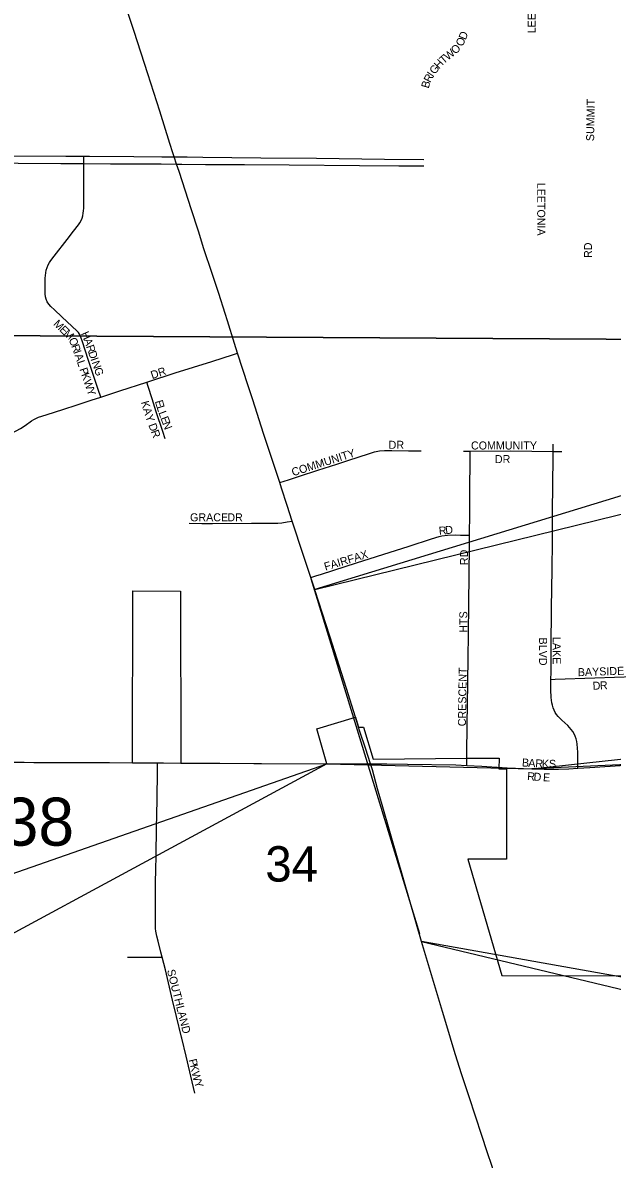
# Model space of a CAD drawing. Extents: x -9.1 to 34, y -3.1 to 22.
# Drawn here: x 5.401 to 6.099, y 17.795 to 19.14 of the extents above; entities that cross this region are included whole.
import ezdxf

# ---------------------------------------------------------------- set-up
doc = ezdxf.new("R2010")
doc.units = 0
for name, color, linetype in [('GM_X_City_Street', 7, 'Continuous'), ('GM_X_City_Street_Text', 7, 'Continuous'), ('GM_X_Corporation', 7, 'Continuous'), ('GM_X_County_Road', 7, 'Continuous'), ('GM_X_County_Road_Text', 7, 'Continuous'), ('GM_X_Section', 7, 'Continuous'), ('GM_X_Section_Text', 7, 'Continuous'), ('GM_X_State_Route', 7, 'Continuous'), ('GM_X_Township_Subdivision', 7, 'Continuous'), ('GM_X_Township_Subdivision_Text', 7, 'Continuous'), ('SH_Data', 7, 'Continuous'), ('SH_Text', 7, 'Continuous')]:
    doc.layers.add(name, color=color, linetype=linetype)

msp = doc.modelspace()

# ---------------------------------------------------------------- linework, layer by layer
at = {"layer": 'GM_X_City_Street'}
for points in [[(5.3542, 18.9769), (5.356, 18.9783), (5.3586, 18.9798), (5.3615, 18.9809), (5.3636, 18.9814), (5.3652, 18.9818), (5.3667, 18.9822), (5.3681, 18.9824), (5.3713, 18.9826), (5.3788, 18.9827), (5.4521, 18.9824), (5.4736, 18.9823)], [(5.3542, 18.9769), (5.3606, 18.9753), (5.3623, 18.9749), (5.3637, 18.9748), (5.3658, 18.9747), (5.3698, 18.9745), (5.3751, 18.9744), (5.3959, 18.9741), (5.4463, 18.9738), (5.471, 18.9736), (5.4736, 18.9736)], [(5.4736, 18.9736), (5.4736, 18.977), (5.4736, 18.9823)], [(5.4736, 18.9823), (5.48, 18.9823), (5.5328, 18.9819), (5.5658, 18.9816), (5.5805, 18.9814)], [(5.5805, 18.9814), (5.5956, 18.9814), (5.6143, 18.9813), (5.6487, 18.9809), (5.6831, 18.9805), (5.7489, 18.9799), (5.8294, 18.9787), (5.8757, 18.9785)], [(5.4934, 18.6971), (5.4905, 18.706), (5.4849, 18.7226), (5.4791, 18.7405), (5.4716, 18.7639), (5.4704, 18.767), (5.4694, 18.7696), (5.4683, 18.7718), (5.4671, 18.7735), (5.4656, 18.7751), (5.4476, 18.792), (5.4388, 18.8003), (5.4344, 18.8045), (5.4321, 18.8073), (5.4302, 18.8101), (5.429, 18.813), (5.4282, 18.816), (5.4278, 18.8192), (5.4278, 18.8318), (5.4278, 18.838), (5.428, 18.8412), (5.4283, 18.8444), (5.429, 18.8475), (5.4299, 18.8506), (5.4311, 18.8536), (5.4327, 18.8564), (5.4344, 18.859), (5.4382, 18.864), (5.4538, 18.8836), (5.4614, 18.8935), (5.4671, 18.9009), (5.4688, 18.9034), (5.4702, 18.906), (5.4713, 18.9088), (5.4722, 18.9117), (5.4728, 18.9147), (5.4732, 18.9177), (5.4734, 18.9208), (5.4734, 18.9301), (5.4736, 18.9676), (5.4736, 18.9736)], [(5.4736, 18.9736), (5.505, 18.9734), (5.5351, 18.9733), (5.559, 18.9732), (5.5651, 18.9732), (5.5833, 18.9729)], [(5.5833, 18.9729), (5.5896, 18.9728), (5.6174, 18.9726), (5.6638, 18.9723), (5.7164, 18.972), (5.7999, 18.9714), (5.8463, 18.971), (5.8757, 18.9707)], [(5.548, 18.7149), (5.5494, 18.7153), (5.5816, 18.7258), (5.625, 18.7395), (5.6507, 18.7476), (5.6555, 18.7492)], [(5.4934, 18.6971), (5.5161, 18.7045), (5.548, 18.7149)], [(5.5699, 18.6478), (5.567, 18.6565), (5.5592, 18.6798), (5.5542, 18.695), (5.5496, 18.7098), (5.548, 18.7149)], [(5.3655, 18.652), (5.3754, 18.6521), (5.3785, 18.6523), (5.3816, 18.6529), (5.3846, 18.6537), (5.3875, 18.6546), (5.3904, 18.6558), (5.3932, 18.6571), (5.3987, 18.6601), (5.404, 18.6636), (5.4116, 18.669), (5.4143, 18.6706), (5.4199, 18.6733), (5.4288, 18.6762), (5.4496, 18.6828), (5.4644, 18.6877), (5.4821, 18.6935), (5.4934, 18.6971)], [(6.0291, 18.633), (6.0291, 18.6416)], [(5.7053, 18.5961), (5.7156, 18.5994), (5.7286, 18.6035), (5.7506, 18.6109), (5.7731, 18.618), (5.787, 18.6224), (5.7982, 18.6262), (5.8117, 18.6305), (5.8175, 18.6323), (5.8234, 18.6336), (5.8295, 18.6339), (5.8382, 18.6339), (5.8577, 18.6338), (5.8726, 18.6336)], [(5.923, 18.6333), (5.9307, 18.6333)], [(5.93, 18.5338), (5.9302, 18.5599), (5.9305, 18.5931), (5.9307, 18.6169), (5.9307, 18.6296), (5.9307, 18.6333)], [(5.9307, 18.6333), (5.9787, 18.6335), (6.0038, 18.6333), (6.0289, 18.633), (6.0291, 18.633)], [(6.0264, 18.3631), (6.0265, 18.3717), (6.0265, 18.4002), (6.027, 18.4478), (6.0278, 18.493), (6.028, 18.5262), (6.0282, 18.5611), (6.0291, 18.6261), (6.0291, 18.633)], [(6.0291, 18.633), (6.0393, 18.633)], [(5.5981, 18.5479), (5.6132, 18.5476), (5.6256, 18.5478), (5.672, 18.5481), (5.6905, 18.5481), (5.703, 18.5482), (5.7079, 18.5485), (5.7142, 18.5495), (5.7202, 18.5505)], [(5.742, 18.4839), (5.7492, 18.4861), (5.7537, 18.4874), (5.7694, 18.4925), (5.7961, 18.501), (5.8198, 18.5085), (5.8584, 18.5209), (5.885, 18.5296), (5.894, 18.5322), (5.8971, 18.5329), (5.9038, 18.5338), (5.9128, 18.5341), (5.9191, 18.534), (5.93, 18.5338)], [(5.9267, 18.2612), (5.9267, 18.2645), (5.9269, 18.2751), (5.9272, 18.3093), (5.9281, 18.3588), (5.9284, 18.39), (5.9287, 18.4152), (5.9292, 18.4536), (5.9295, 18.4856), (5.9299, 18.5233), (5.93, 18.5338)], [(6.0582, 18.258), (6.0582, 18.2648), (6.0583, 18.2679), (6.058, 18.2772), (6.0574, 18.2865), (6.057, 18.2896), (6.0562, 18.2927), (6.0552, 18.2958), (6.0539, 18.2987), (6.0522, 18.3014), (6.0503, 18.304), (6.0462, 18.3087), (6.0394, 18.315), (6.035, 18.3193), (6.0331, 18.3216), (6.0315, 18.3241), (6.0301, 18.3268), (6.029, 18.3296), (6.0281, 18.3325), (6.0275, 18.3354), (6.0267, 18.3417), (6.0263, 18.3507), (6.0264, 18.3631)], [(6.0264, 18.3631), (6.0314, 18.3633), (6.0783, 18.365), (6.1247, 18.3666)], [(5.9744, 18.2585), (6.0037, 18.2573), (6.0182, 18.2568), (6.0352, 18.257), (6.0476, 18.2574), (6.0582, 18.258)], [(6.0582, 18.258), (6.0725, 18.2588), (6.1141, 18.2617)]]:
    msp.add_lwpolyline(points, dxfattribs=at)
at = {"layer": 'GM_X_Corporation'}
msp.add_lwpolyline([(5.2741, 18.2659), (5.5312, 18.2646), (5.5316, 18.4678), (5.5879, 18.4677), (5.5884, 18.2642), (5.7611, 18.2634), (5.7493, 18.3046), (5.7952, 18.3185), (5.7987, 18.3068), (5.8046, 18.3068), (5.816, 18.2689), (5.9268, 18.2698), (5.965, 18.2701), (5.9648, 18.2573), (5.9736, 18.2572), (5.9736, 18.1503), (5.928, 18.1504), (5.9683, 18.0127), (6.1445, 18.0123)], dxfattribs=at)
at = {"layer": 'GM_X_County_Road'}
for points in [[(5.3581, 18.2653), (5.374, 18.2651), (5.4142, 18.2648), (5.4389, 18.2648), (5.4698, 18.265), (5.5039, 18.2647), (5.5312, 18.2646)], [(5.5312, 18.2646), (5.5554, 18.2644), (5.5606, 18.2643)], [(5.5606, 18.2643), (5.5676, 18.2643), (5.5884, 18.2642)], [(5.5884, 18.2642), (5.6068, 18.2641), (5.6345, 18.2639), (5.6838, 18.2638), (5.7611, 18.2634)], [(5.7611, 18.2634), (5.7934, 18.2633), (5.8003, 18.2632), (5.8104, 18.2631), (5.8129, 18.2631)], [(5.8129, 18.2631), (5.832, 18.2634), (5.8567, 18.2629), (5.9137, 18.2619), (5.9267, 18.2612)], [(5.9267, 18.2612), (5.9446, 18.2603), (5.9744, 18.2585)]]:
    msp.add_lwpolyline(points, dxfattribs=at)
at = {"layer": 'GM_X_Section'}
for points in [[(5.226, 19.7723), (6.2379, 19.7608), (6.2253, 18.7649), (5.2207, 18.771)], [(5.2207, 18.771), (6.2253, 18.7649), (6.224, 17.7617), (5.2149, 17.764)]]:
    msp.add_lwpolyline(points, close=True, dxfattribs=at)
at = {"layer": 'GM_X_State_Route'}
for points in [[(5.5805, 18.9814), (5.579, 18.9862), (5.5754, 18.9971), (5.5633, 19.0354), (5.5491, 19.0797), (5.5329, 19.1297), (5.528, 19.145), (5.5046, 19.2183), (5.4949, 19.2478), (5.4882, 19.2683), (5.4825, 19.2859), (5.4738, 19.3125)], [(5.6435, 18.7873), (5.6407, 18.7961), (5.6332, 18.8198), (5.6255, 18.8434), (5.6156, 18.8728), (5.609, 18.8934), (5.6005, 18.9201), (5.5937, 18.9407), (5.5862, 18.9641), (5.5833, 18.9729), (5.5805, 18.9814)], [(5.6733, 18.694), (5.668, 18.7104), (5.6555, 18.7492), (5.6518, 18.7606), (5.6435, 18.7873)], [(5.7467, 18.4697), (5.742, 18.4839), (5.7334, 18.5099), (5.7202, 18.5505), (5.7143, 18.5689), (5.7074, 18.5896), (5.7053, 18.5961), (5.686, 18.6543), (5.6733, 18.694)], [(5.7951, 18.3184), (5.7845, 18.3523), (5.7648, 18.4142), (5.7473, 18.4678), (5.7467, 18.4697)], [(5.8007, 18.3002), (5.7999, 18.3026), (5.7951, 18.3184)], [(5.8265, 18.2149), (5.8211, 18.2337), (5.815, 18.2562), (5.8129, 18.2631), (5.8067, 18.2819), (5.8007, 18.3002)], [(5.9018, 17.9573), (5.8979, 17.9701), (5.8733, 18.0531), (5.8446, 18.1517), (5.8265, 18.2149)], [(5.9596, 17.7774), (5.9566, 17.7867), (5.9509, 17.8042), (5.9446, 17.8235), (5.9295, 17.8693), (5.9249, 17.8833), (5.9205, 17.8964), (5.9133, 17.9189), (5.9129, 17.9199), (5.9018, 17.9573)]]:
    msp.add_lwpolyline(points, dxfattribs=at)
at = {"layer": 'GM_X_Township_Subdivision'}
for points in [[(5.5584, 18.1244), (5.5586, 18.1368), (5.5589, 18.1554), (5.5595, 18.1866), (5.5601, 18.2208), (5.5602, 18.227), (5.5607, 18.2488), (5.5606, 18.2579), (5.5606, 18.2643)], [(5.5662, 18.0343), (5.5647, 18.0403), (5.5614, 18.0533), (5.5598, 18.0593), (5.5587, 18.0652), (5.5583, 18.0682), (5.5581, 18.0714), (5.5581, 18.0899), (5.5584, 18.1243), (5.5584, 18.1244)], [(5.525, 18.0346), (5.5329, 18.0345), (5.5485, 18.0343), (5.5614, 18.0343), (5.5662, 18.0343)], [(5.5892, 17.9398), (5.5832, 17.9642), (5.5784, 17.9836), (5.57, 18.0195), (5.5662, 18.0343)], [(5.6049, 17.8735), (5.6016, 17.8868), (5.5946, 17.9172), (5.5896, 17.9385), (5.5892, 17.9398)]]:
    msp.add_lwpolyline(points, dxfattribs=at)
at = {"layer": 'SH_Data'}
for p, q in [((5.871, 18.0621), (5.7427, 18.4823)), ((5.7611, 18.2634), (6.0037, 18.2573))]:
    msp.add_line(p, q, dxfattribs=at)
at = {"layer": 'SH_Text'}
for points in [[(9.6799, 19.6726), (5.7467, 18.4697), (9.6799, 19.4366)], [(9.7171, 18.426), (6.0037, 18.2573), (9.7171, 18.662)], [(4.5258, 17.8317), (5.7611, 18.2634), (4.5258, 17.5957)], [(9.7227, 17.3677), (5.8733, 18.0531), (9.7227, 17.1316)]]:
    msp.add_lwpolyline(points, close=True, dxfattribs=at)

# ---------------------------------------------------------------- texts
at = {"layer": 'GM_X_City_Street_Text'}
for s, rotation, p in [('LEETONIA', 90, (6.0082, 19.1276)), ('D', 67.4768, (5.9253, 19.1192)), ('O', 42.1808, (5.9131, 19.1023)), ('O', 65.587, (5.9217, 19.1113)), ('T', 40.8235, (5.8994, 19.0908)), ('W', 39.558, (5.9044, 19.0951)), ('G', 52.1729, (5.889, 19.0784)), ('H', 47.8601, (5.894, 19.0848)), ('B', 73.5543, (5.8815, 19.0619)), ('R', 62.6747, (5.8835, 19.0686)), ('I', 56.0069, (5.8868, 19.0751)), ('SUMMIT', 88.9976, (6.0774, 19)), ('LEETONIA', 270, (6.0101, 18.9509)), ('RD', 90, (6.0749, 18.8618)), ('M', 316.2622, (5.4367, 18.7829)), ('E', 316.2559, (5.4439, 18.776)), ('M', 316.1849, (5.4487, 18.7714)), ('H', 293.1326, (5.47, 18.7725)), ('O', 292.2803, (5.4553, 18.7654)), ('A', 289.942, (5.4732, 18.765)), ('R', 289.9478, (5.4584, 18.7577)), ('I', 289.2921, (5.461, 18.7507)), ('R', 289.1032, (5.476, 18.7572)), ('D', 289.1041, (5.4785, 18.7501)), ('A', 289.1054, (5.4624, 18.7468)), ('L', 289.1166, (5.4651, 18.7389)), ('I', 289.0983, (5.4812, 18.7422)), ('N', 289.0848, (5.4826, 18.7383)), ('P', 289.0924, (5.4681, 18.7302)), ('K', 289.0848, (5.4703, 18.724)), ('G', 289.1041, (5.4853, 18.7304)), ('DR', 18.4349, (5.5544, 18.7184)), ('W', 289.0987, (5.473, 18.7161)), ('Y', 289.1054, (5.4765, 18.7058)), ('E', 286.058, (5.5575, 18.6922)), ('K', 285.7593, (5.541, 18.6912)), ('A', 287.544, (5.5434, 18.6829)), ('L', 287.5568, (5.5594, 18.6856)), ('L', 290.2881, (5.5616, 18.6788)), ('Y', 289.1396, (5.546, 18.6746)), ('E', 290.7775, (5.564, 18.6724)), ('N', 290.7786, (5.5663, 18.6662)), ('D', 290.4085, (5.5497, 18.6642)), ('R', 290.5478, (5.5526, 18.6564)), ('DR', 0, (5.8342, 18.636)), ('COMMUNITY', 0, (5.9317, 18.6352)), ('COMMUNITY', 17.6235, (5.7211, 18.6035)), ('DR', 0, (5.96, 18.6191)), ('GRACE', 0, (5.5992, 18.5502)), ('DR', 0, (5.6433, 18.5502)), ('R', 5.0339, (5.894, 18.5342)), ('D', 6.2692, (5.9017, 18.5349)), ('FAIRFAX', 16.8853, (5.7595, 18.4917)), ('RD', 90, (5.9282, 18.4984)), ('HTS', 90, (5.9274, 18.4184)), ('BLVD', 270, (6.0123, 18.4126)), ('LAKE', 270, (6.0285, 18.4134)), ('CRESCENT', 89.1935, (5.9257, 18.3076)), ('BAYSIDE', 1.9081, (6.0583, 18.3669)), ('D', 2.4051, (6.0759, 18.3508)), ('R', 3.5013, (6.0845, 18.3511)), ('B', 356.4524, (5.9918, 18.2602)), ('A', 356.4573, (5.9993, 18.2597)), ('R', 356.4742, (6.0076, 18.2592)), ('K', 358.6528, (6.0155, 18.2587)), ('S', 359.9457, (6.024, 18.2585)), ('R', 355.065, (5.9979, 18.2441)), ('D', 355.4739, (6.0055, 18.2435)), ('E', 358.1874, (6.0168, 18.2426))]:
    msp.add_text(s, height=0.00947, rotation=rotation, dxfattribs=at).set_placement(p)
at = {"layer": 'GM_X_County_Road_Text'}
msp.add_text('C-138', height=0.05682, rotation=0, dxfattribs=at).set_placement((5.255, 18.1664))
at = {"layer": 'GM_X_Section_Text'}
msp.add_text('34', height=0.04186, rotation=0, dxfattribs=at).set_placement((5.6883, 18.1239))
at = {"layer": 'GM_X_Township_Subdivision_Text'}
for s, rotation, p in [('SOUTHLAND', 284.1975, (5.5718, 18.0188)), ('P', 282.8103, (5.5976, 17.913)), ('K', 282.7849, (5.5991, 17.9065)), ('W', 283.5094, (5.6009, 17.8982)), ('Y', 288.9447, (5.6037, 17.8868))]:
    msp.add_text(s, height=0.00947, rotation=rotation, dxfattribs=at).set_placement(p)

doc.saveas('drawing.dxf')
